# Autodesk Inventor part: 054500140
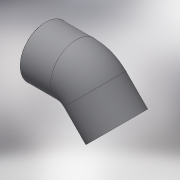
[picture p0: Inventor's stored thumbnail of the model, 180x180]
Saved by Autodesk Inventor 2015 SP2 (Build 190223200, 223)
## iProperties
Created: 2017-10
Part Number: 054500140
Material: Generic
Description: PLASSON 45° ELBOW CEMENT PVC 140
Document SubType Name: Modeling
Designer: KIM
Density: 1 g/cm^3
Appearance: Default
Author: KIM
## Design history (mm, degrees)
derived "054500.ipt"
feature "Solid1::054500.ipt"
tag "TaggingFeature1"
body "Solid1"
other parameters: "d1" = 163, "d5" = 126, "d7" = 1.4, "d9" = 163, "d13" = 135 deg, "d18" = 31, "d19" = 45 deg, "d21" = 76, "d22" = 0, "d24" = 135 deg, "d26" = 126, "d27" = 45 deg, "d28" = 107, "E_" = 163, "H_" = 35, "l_" = 76, "Z_" = 31
